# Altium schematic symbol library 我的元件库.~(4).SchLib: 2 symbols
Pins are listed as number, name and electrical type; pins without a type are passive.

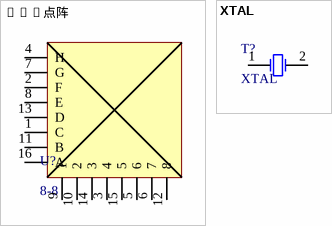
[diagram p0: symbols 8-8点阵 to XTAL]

## 8-8点阵
designator U?, comment 8-8
8-8: RAD
footprint 8-8LED点阵 - duplicate
pins: 1 C, 2 F, 3 4, 4 H, 5 6, 6 7, 7 G, 8 E, 9 1, 10 2, 11 B, 12 8, 13 D, 14 3, 15 5, 16 A

## XTAL
designator T?
XTAL: 12MHZ
footprint XTAL
pins: 1, 2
